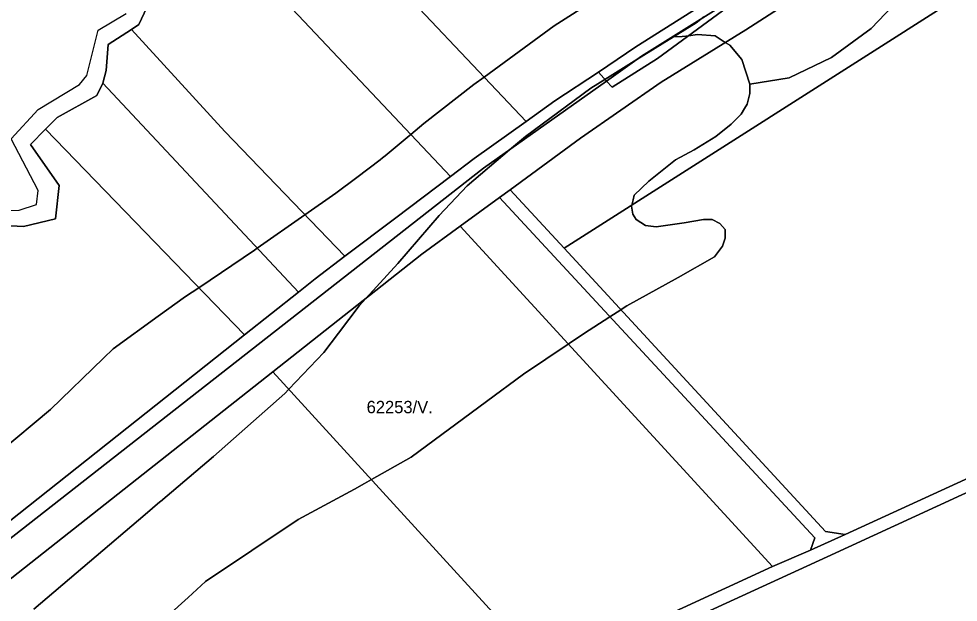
# Model space of a CAD drawing. Extents: x -522079 to -518833, y -1142400 to -1139961.
# Drawn here: x -521365.3 to -520985.3, y -1140523.8 to -1140287.7 of the extents above; entities that cross this region are included whole.
import ezdxf

# ---------------------------------------------------------------- set-up
doc = ezdxf.new("R2010")
doc.units = 0
for name, color, linetype in [('95560013', 7, 'Continuous'), ('95610013', 7, 'Continuous'), ('95630013', 7, 'Continuous'), ('95640013', 7, 'Continuous'), ('95660013', 7, 'Continuous')]:
    doc.layers.add(name, color=color, linetype=linetype)

msp = doc.modelspace()

# ---------------------------------------------------------------- linework, layer by layer
at = {"layer": '95560013'}
for points in [[(-521144.75, -1140380.49), (-521166.55, -1140356.84), (-521138.04, -1140336), (-521105.44, -1140313.39), (-521071.25, -1140292.13), (-521029.36, -1140265.01), (-520991.34, -1140239.5), (-520978.89, -1140274.79)], [(-521042, -1140261.25), (-521029.36, -1140265.01), (-521071.25, -1140292.13), (-521105.44, -1140313.39), (-521138.04, -1140336), (-521166.55, -1140356.84), (-521170.88, -1140360.01), (-521186.8, -1140371.65), (-521202.24, -1140382.94), (-521262.52, -1140430.5), (-521393.25, -1140533.65), (-521431, -1140563.44), (-521501.14, -1140618.78), (-521510.5, -1140608.85), (-521177.32, -1140348.18), (-521127.62, -1140312.94), (-521125.23, -1140315.3), (-521106.97, -1140303.78), (-521080.73, -1140284.42), (-521065.28, -1140272.43), (-521054.61, -1140266.48)], [(-521113.39, -1140302.86), (-521069.26, -1140274.95), (-521065.28, -1140272.43), (-521080.73, -1140284.42), (-521106.97, -1140303.78), (-521125.23, -1140315.3), (-521127.62, -1140312.94)], [(-520943.46, -1140405.56), (-520937.19, -1140417.44), (-520924.28, -1140409.64), (-520923.06, -1140411.9), (-520913.58, -1140428.33), (-520906.37, -1140439.12), (-521031.07, -1140496.4), (-521039.03, -1140495.22), (-521144.75, -1140380.49), (-520978.89, -1140274.79), (-520959.74, -1140329.07), (-520948.85, -1140357.77), (-520931.92, -1140395.43), (-520930.52, -1140398.04)], [(-521031.07, -1140496.4), (-521045.09, -1140502.65), (-521043.27, -1140497.72), (-521170.88, -1140360.01), (-521166.55, -1140356.84), (-521144.75, -1140380.49), (-521039.03, -1140495.22)], [(-521170.88, -1140360.01), (-521043.27, -1140497.72), (-521045.09, -1140502.65), (-521060.49, -1140509.3), (-521186.8, -1140371.65)], [(-521060.49, -1140509.3), (-521152, -1140551.52), (-521262.52, -1140430.5), (-521202.24, -1140382.94), (-521186.8, -1140371.65)], [(-521309.07, -1140623.96), (-521393.25, -1140533.65), (-521262.52, -1140430.5), (-521152, -1140551.52)], [(-521174.07, -1140567.72), (-521038.29, -1140505.39), (-520903.84, -1140443.54), (-520902.4, -1140445.74), (-520890.58, -1140462.46), (-520871.65, -1140486.28), (-520862.22, -1140497.87), (-521134.28, -1140622.71), (-521175.11, -1140573.76)]]:
    msp.add_lwpolyline(points, close=True, dxfattribs=at)
at = {"layer": '95610013'}
for points in [[(-521303.57, -1140232.09), (-521288.02, -1140193.37), (-521224.97, -1140260.52), (-521160.13, -1140329.24), (-521181.05, -1140344.19), (-521190.73, -1140351.49), (-521249.83, -1140288.83)], [(-521319.77, -1140291.98), (-521316.7, -1140289.98), (-521313.45, -1140283.14), (-521313.53, -1140260.28), (-521303.57, -1140232.09), (-521249.83, -1140288.83), (-521190.73, -1140351.49), (-521212.85, -1140368.17), (-521233.39, -1140383.74), (-521281.93, -1140333.33)], [(-521331.35, -1140313.68), (-521329.93, -1140308.65), (-521329.18, -1140298.1), (-521319.77, -1140291.98), (-521281.93, -1140333.33), (-521233.39, -1140383.74), (-521245.45, -1140392.88), (-521252.22, -1140398.25)], [(-521349.83, -1140327.64), (-521333.68, -1140318.76), (-521331.35, -1140313.68), (-521252.22, -1140398.25), (-521274.04, -1140415.55), (-521354.5, -1140332.33)], [(-521443.44, -1140442.21), (-521430.97, -1140433.67), (-521425.29, -1140415.18), (-521414.4, -1140412.25), (-521409.97, -1140408.74), (-521387.23, -1140382.25), (-521376.68, -1140371.11), (-521363.37, -1140371.78), (-521350.48, -1140368.68), (-521348.98, -1140355.15), (-521360.62, -1140338.49), (-521354.5, -1140332.33), (-521274.04, -1140415.55), (-521389.53, -1140507.12), (-521435.8, -1140458.35), (-521435.3, -1140455)]]:
    msp.add_lwpolyline(points, close=True, dxfattribs=at)
msp.add_lwpolyline([(-521081.77, -1140277.41), (-521115.76, -1140299), (-521130.86, -1140309.33), (-521148.51, -1140320.94), (-521160.13, -1140329.24), (-521224.97, -1140260.52)], dxfattribs=at)
at = {"layer": '95630013'}
for points in [[(-521313.45, -1140283.14), (-521316.7, -1140289.98), (-521319.77, -1140291.98), (-521329.18, -1140298.1), (-521329.93, -1140308.65), (-521331.35, -1140313.68), (-521333.68, -1140318.76), (-521349.83, -1140327.64), (-521354.5, -1140332.33), (-521360.62, -1140338.49), (-521348.98, -1140355.15), (-521350.48, -1140368.68), (-521363.37, -1140371.78), (-521376.68, -1140371.11)], [(-521379.07, -1140365.7), (-521365.2, -1140365.12), (-521358.18, -1140362.8), (-521357.5, -1140357.21), (-521368.43, -1140336.25), (-521357.43, -1140324.38), (-521340.77, -1140314.23), (-521337.76, -1140310.68), (-521333.16, -1140292.26), (-521321.89, -1140285.5)]]:
    msp.add_lwpolyline(points, dxfattribs=at)
at = {"layer": '95640013'}
for points in [[(-521115.76, -1140299), (-521081.77, -1140277.41), (-521071.39, -1140271.24), (-521069.26, -1140274.95), (-521113.39, -1140302.86), (-521127.62, -1140312.94), (-521130.86, -1140309.33)], [(-521245.45, -1140392.88), (-521233.39, -1140383.74), (-521212.85, -1140368.17), (-521190.73, -1140351.49), (-521181.05, -1140344.19), (-521160.13, -1140329.24), (-521148.51, -1140320.94), (-521130.86, -1140309.33), (-521127.62, -1140312.94), (-521177.32, -1140348.18), (-521510.5, -1140608.85), (-521513.48, -1140605.69), (-521389.53, -1140507.12), (-521274.04, -1140415.55), (-521252.22, -1140398.25)], [(-521428.47, -1140683.93), (-521438.02, -1140688.47), (-521441.99, -1140684.63), (-521355.48, -1140644.9), (-521309.07, -1140623.96), (-521152, -1140551.52), (-521060.49, -1140509.3), (-521045.09, -1140502.65), (-521031.07, -1140496.4), (-520906.37, -1140439.12), (-520903.84, -1140443.54), (-521038.29, -1140505.39), (-521174.07, -1140567.72), (-521187.8, -1140573.75), (-521306.81, -1140628.37)]]:
    msp.add_lwpolyline(points, close=True, dxfattribs=at)
at = {"layer": '95660013'}
for points in [[(-521311.93, -1140535.49), (-521296.83, -1140521.82), (-521289.79, -1140515.44), (-521252.24, -1140490.24), (-521229.55, -1140478.05), (-521225.41, -1140475.7), (-521222.66, -1140474.14), (-521206.6, -1140465.04), (-521176.08, -1140442.55), (-521161.22, -1140431.44), (-521143.07, -1140419.31), (-521136.91, -1140415.19), (-521126.19, -1140408.24), (-521121.8, -1140405.39), (-521120.88, -1140404.8), (-521119.35, -1140403.81), (-521098.56, -1140392.43), (-521083.97, -1140384.03), (-521080.73, -1140379.69), (-521079.65, -1140376.44), (-521079.65, -1140372.92), (-521081.81, -1140370.48), (-521084.78, -1140368.85), (-521088.29, -1140368.85), (-521096.13, -1140370.21), (-521107.47, -1140371.83), (-521111.79, -1140371.29), (-521115.57, -1140368.85), (-521116.92, -1140366.69), (-521117.46, -1140363.44), (-521117.4, -1140363.19), (-521117.37, -1140363.04), (-521116.86, -1140361), (-521116.38, -1140359.1), (-521110.44, -1140353.41), (-521099.64, -1140344.74), (-521092.08, -1140340.68), (-521083.43, -1140335.26), (-521077.22, -1140330.38), (-521073.17, -1140326.32), (-521071.78, -1140324), (-521070.74, -1140322.25), (-521069.66, -1140317.92), (-521069.66, -1140314.12), (-521053.67, -1140311.59), (-521036.58, -1140303.28), (-521020.52, -1140291.59), (-521006.02, -1140276.26)], [(-521006.02, -1140276.26), (-521020.52, -1140291.59), (-521036.58, -1140303.28), (-521053.67, -1140311.59), (-521069.66, -1140314.12), (-521072.9, -1140304.1), (-521077.76, -1140298.41), (-521079.53, -1140297.28), (-521083.7, -1140294.61), (-521090.72, -1140294.07), (-521094.48, -1140294.57), (-521095.55, -1140294.7), (-521096.94, -1140294.88), (-521100.44, -1140295.01), (-521091.26, -1140289.33), (-521088.2, -1140286.93)], [(-521130.6, -1140278.79), (-521148.82, -1140290.47), (-521177.07, -1140311.28), (-521181.2, -1140314.33), (-521201.45, -1140330.07), (-521206.77, -1140334.49), (-521207.36, -1140334.98), (-521217.11, -1140343.09), (-521218.18, -1140343.98), (-521219.16, -1140344.78), (-521228.64, -1140351.89), (-521237.12, -1140358.24), (-521249.54, -1140366.96), (-521268.83, -1140380.5), (-521270.02, -1140381.34), (-521292.47, -1140396.49), (-521297.85, -1140400.12), (-521308.89, -1140408.04), (-521327.2, -1140421.19), (-521331.09, -1140424.97), (-521352.5, -1140445.81), (-521373.25, -1140463.07)], [(-521373.25, -1140463.07), (-521352.5, -1140445.81), (-521331.09, -1140424.97), (-521327.2, -1140421.19), (-521308.89, -1140408.04), (-521297.85, -1140400.12), (-521292.47, -1140396.49), (-521270.02, -1140381.34), (-521268.83, -1140380.5), (-521249.54, -1140366.96), (-521237.12, -1140358.24), (-521228.64, -1140351.89), (-521219.16, -1140344.78), (-521218.18, -1140343.98), (-521217.11, -1140343.09), (-521207.36, -1140334.98), (-521206.77, -1140334.49), (-521201.45, -1140330.07), (-521181.2, -1140314.33), (-521177.07, -1140311.28), (-521148.82, -1140290.47), (-521130.6, -1140278.79)], [(-521379.07, -1140365.7), (-521365.2, -1140365.12), (-521358.18, -1140362.8), (-521357.5, -1140357.21), (-521368.43, -1140336.25), (-521357.43, -1140324.38), (-521340.77, -1140314.23), (-521337.76, -1140310.68), (-521333.16, -1140292.26), (-521321.89, -1140285.5)], [(-521088.2, -1140286.93), (-521091.26, -1140289.33), (-521100.44, -1140295.01), (-521115.27, -1140304.19), (-521128.26, -1140312.23), (-521133.94, -1140315.75), (-521160.41, -1140335.26), (-521166.87, -1140340.77), (-521183.91, -1140355.31), (-521195.25, -1140367.23), (-521212, -1140386.74), (-521224.97, -1140400.87), (-521227.66, -1140403.81), (-521236.04, -1140414.91), (-521241.98, -1140422.77), (-521256.03, -1140437.6), (-521257.64, -1140439.3), (-521286.54, -1140464.77), (-521307.94, -1140482.96), (-521308.2, -1140483.19), (-521314.13, -1140488.23), (-521359.2, -1140526.55)], [(-521359.2, -1140526.55), (-521314.13, -1140488.23), (-521308.2, -1140483.19), (-521307.94, -1140482.96), (-521286.54, -1140464.77), (-521257.64, -1140439.3), (-521256.03, -1140437.6), (-521241.98, -1140422.77), (-521236.04, -1140414.91), (-521227.66, -1140403.81), (-521224.97, -1140400.87), (-521212, -1140386.74), (-521195.25, -1140367.23), (-521183.91, -1140355.31), (-521166.87, -1140340.77), (-521160.41, -1140335.26), (-521133.94, -1140315.75), (-521128.26, -1140312.23), (-521115.27, -1140304.19), (-521100.44, -1140295.01), (-521096.94, -1140294.88), (-521095.55, -1140294.7), (-521094.48, -1140294.57), (-521090.72, -1140294.07), (-521083.7, -1140294.61), (-521079.53, -1140297.28), (-521077.76, -1140298.41), (-521072.9, -1140304.1), (-521069.66, -1140314.12), (-521069.66, -1140317.92), (-521070.74, -1140322.25), (-521071.78, -1140324), (-521073.17, -1140326.32), (-521077.22, -1140330.38), (-521083.43, -1140335.26), (-521092.08, -1140340.68), (-521099.64, -1140344.74), (-521110.44, -1140353.41), (-521116.38, -1140359.1), (-521116.86, -1140361), (-521117.37, -1140363.04), (-521117.4, -1140363.19), (-521117.46, -1140363.44), (-521116.92, -1140366.69), (-521115.57, -1140368.85), (-521111.79, -1140371.29), (-521107.47, -1140371.83), (-521096.13, -1140370.21), (-521088.29, -1140368.85), (-521084.78, -1140368.85), (-521081.81, -1140370.48), (-521079.65, -1140372.92), (-521079.65, -1140376.44), (-521080.73, -1140379.69), (-521083.97, -1140384.03), (-521098.56, -1140392.43), (-521119.35, -1140403.81), (-521120.88, -1140404.8), (-521121.8, -1140405.39), (-521126.19, -1140408.24), (-521136.91, -1140415.19), (-521143.07, -1140419.31), (-521161.22, -1140431.44), (-521176.08, -1140442.55), (-521206.6, -1140465.04), (-521222.66, -1140474.14), (-521225.41, -1140475.7), (-521229.55, -1140478.05), (-521252.24, -1140490.24), (-521289.79, -1140515.44), (-521296.83, -1140521.82), (-521311.93, -1140535.49)]]:
    msp.add_lwpolyline(points, dxfattribs=at)

# ---------------------------------------------------------------- texts
msp.add_text('62253/V.', height=5, rotation=360, dxfattribs=at).set_placement((-521224.61, -1140447.29))

doc.saveas('drawing.dxf')
